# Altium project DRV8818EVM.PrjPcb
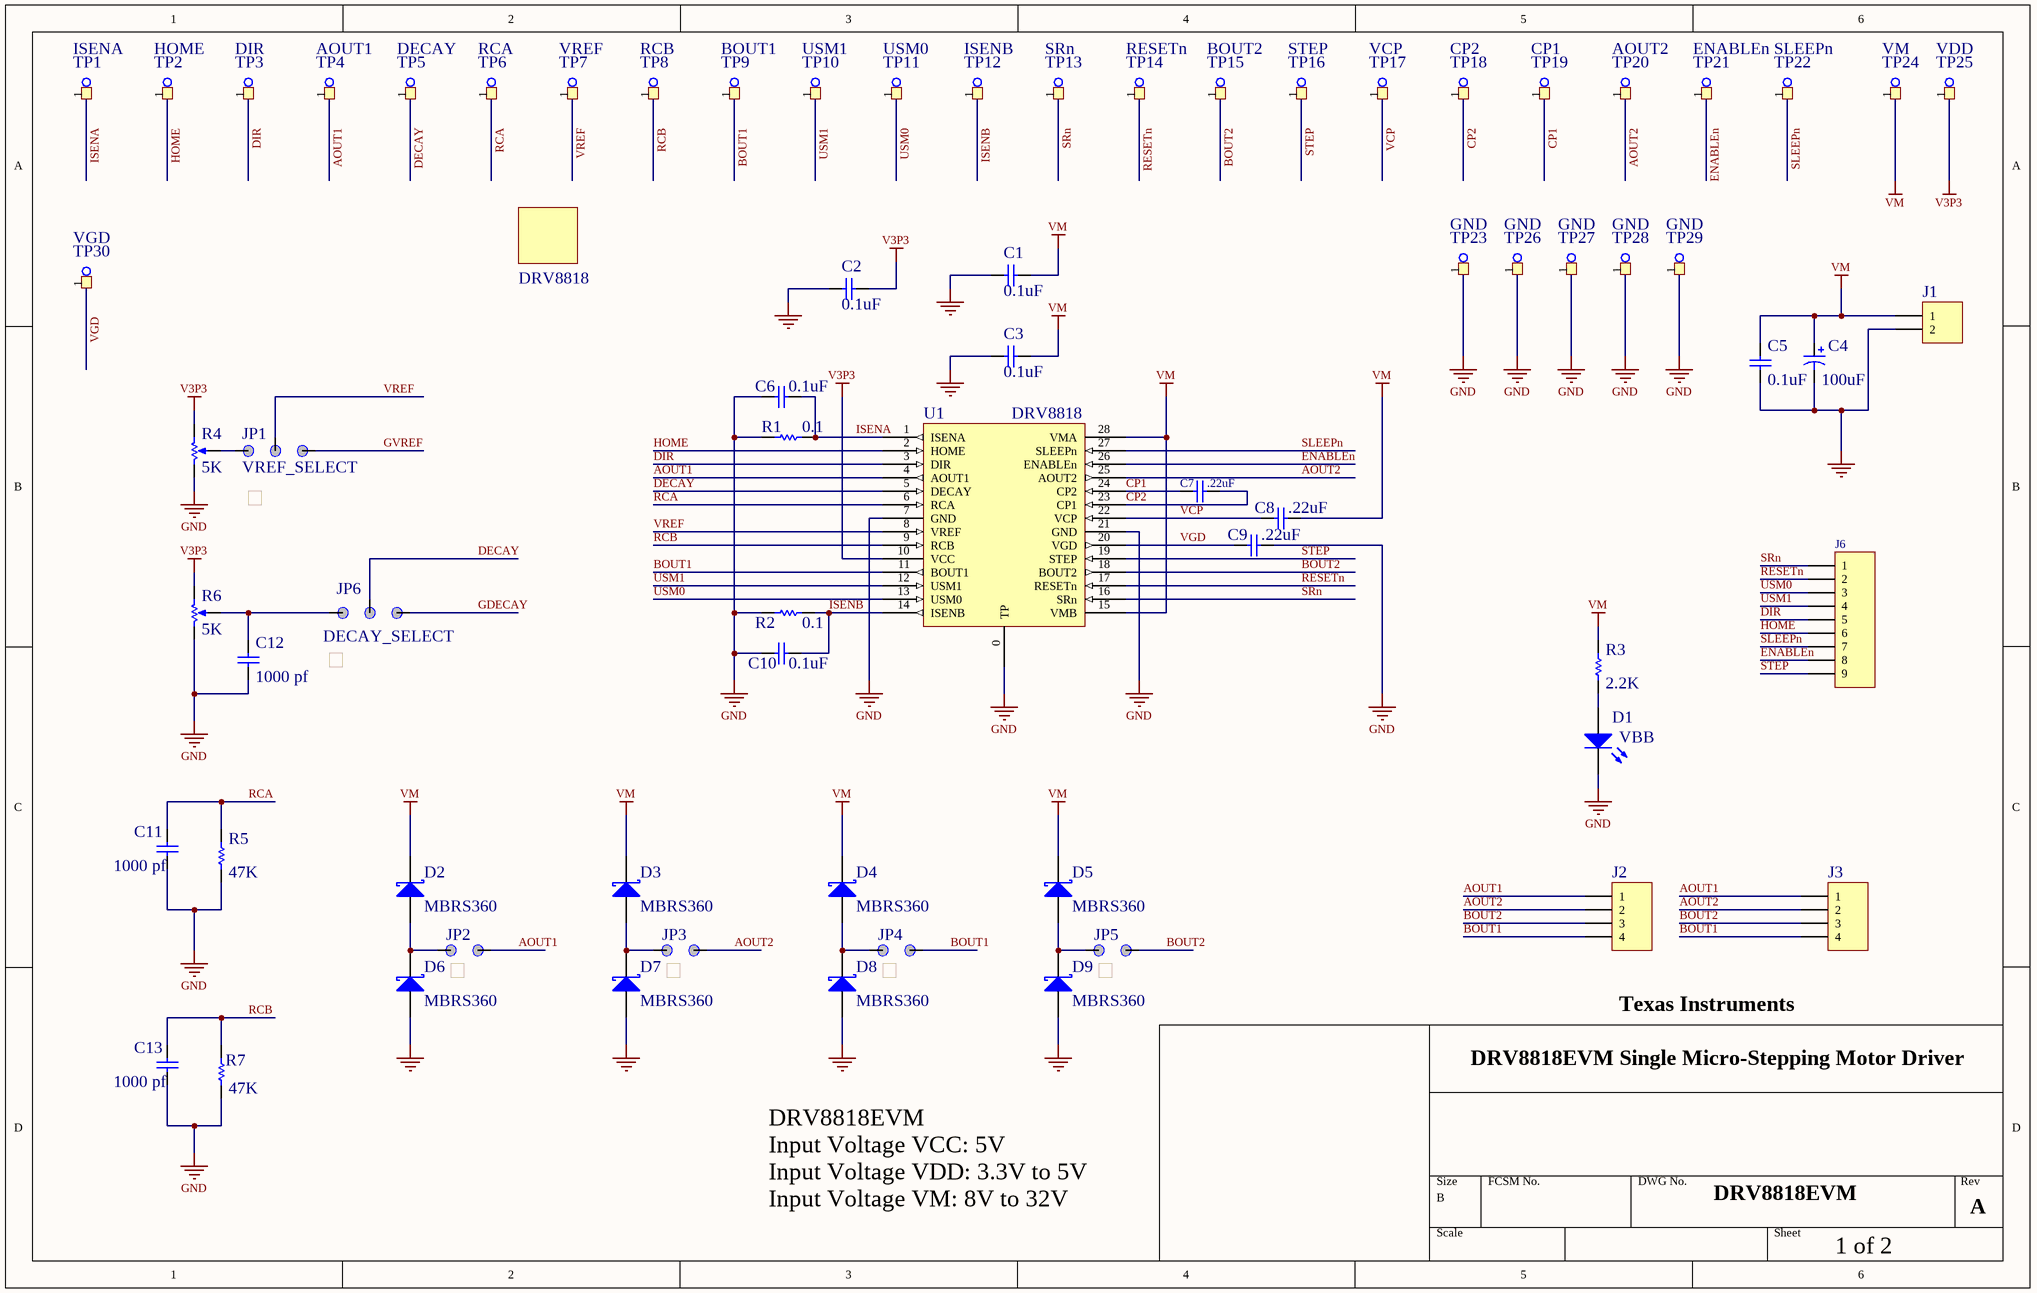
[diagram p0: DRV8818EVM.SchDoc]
2 sheets, 115 parts. Net scope: global (net labels, ports and power ports of the same name join across sheets).
Board file: DRV8818EVM.PcbDoc
Sheets:
  DRV8818EVM.SchDoc
  DRV8818EVM_MSP430.SchDoc

## Sheet DRV8818EVM.SchDoc: Texas Instruments - DRV8818 Customer EVM
size B; PageSetup: Record=PageOptions|CenterHorizontal=True|CenterVertical=True|PrintScale=1.00|XCorrection=1.00|YCorrection=1.00|PrintKind=0|BorderSize=5000000|LeftOffset=0|BottomOffset=0|Orientation=2|PaperLength=1000|PaperWidth=1000|Scale=100|PaperSource=7|PrintQuality=-4|MediaType=1|DitherType=10|PaperKind=Letter|PrintScaleMode=1

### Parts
C1  value 0.1uF  [0805]
C2  value 0.1uF  [0805]
C3  value 0.1uF  [0805]
C4  value 100uF  [RB .2/.4 SS]
C5  value 0.1uF  [0805]
C6  value 0.1uF  [0805]
C7  value .22uF  [0805]  (hidden comment: .1uF)
C8  value .22uF  [0805]  (hidden comment: .1uF)
C9  value .22uF  [0805]  (hidden comment: .1uF)
C10  value 0.1uF  [0805]
C11  value 1000 pf  [0805]
C12  value 1000 pf  [0805]
C13  value 1000 pf  [0805]
D1  VBB  [1206_LED]
D2  MBRS360  [SMC-W]
D3  MBRS360  [SMC-W]
D4  MBRS360  [SMC-W]
D5  MBRS360  [SMC-W]
D6  MBRS360  [SMC-W]
D7  MBRS360  [SMC-W]
D8  MBRS360  [SMC-W]
D9  MBRS360  [SMC-W]
J1  Header 2  [PWR_CONN2]  (value not drawn)
J2  Header 4  [HDR1X4]  (value not drawn)
J3  Header 4  [PWR_CONN4]  (value not drawn)
J6  Header 9  [HDR1X9]  (value not drawn)
JP1  VREF_SELECT  [JMP0.3]
JP2  JUMPER 2 PIN  [JMP0.2]  (value not drawn)
JP3  JUMPER 2 PIN  [JMP0.2]  (value not drawn)
JP4  JUMPER 2 PIN  [JMP0.2]  (value not drawn)
JP5  JUMPER 2 PIN  [JMP0.2]  (value not drawn)
JP6  DECAY_SELECT  [JMP0.3]
PCB1  DRV8818  [TI_LOGO]
R1  value 0.1  [2512]
R2  value 0.1  [2512]
R3  value 2.2K  [0805]  (hidden comment: Res1)
R4  value 5K  [VR5]
R5  value 47K  [0805]
R6  value 5K  [VR5]
R7  value 47K  [0805]
SHNT1  3 pin Jumper Shunt  (value not drawn)
SHNT2  3 pin Jumper Shunt  (value not drawn)
SHNT3  3 pin Jumper Shunt  (value not drawn)
SHNT4  3 pin Jumper Shunt  (value not drawn)
SHNT5  3 pin Jumper Shunt  (value not drawn)
SHNT6  3 pin Jumper Shunt  (value not drawn)
TP1  ISENA  [TEST POINT 0.052]
TP2  HOME  [TEST POINT 0.052]
TP3  DIR  [TEST POINT 0.052]
TP4  AOUT1  [TEST POINT 0.052]
TP5  DECAY  [TEST POINT 0.052]
TP6  RCA  [TEST POINT 0.052]
TP7  VREF  [TEST POINT 0.052]
TP8  RCB  [TEST POINT 0.052]
TP9  BOUT1  [TEST POINT 0.052]
TP10  USM1  [TEST POINT 0.052]
TP11  USM0  [TEST POINT 0.052]
TP12  ISENB  [TEST POINT 0.052]
TP13  SRn  [TEST POINT 0.052]
TP14  RESETn  [TEST POINT 0.052]
TP15  BOUT2  [TEST POINT 0.052]
TP16  STEP  [TEST POINT 0.052]
TP17  VCP  [TEST POINT 0.052]
TP18  CP2  [TEST POINT 0.052]
TP19  CP1  [TEST POINT 0.052]
TP20  AOUT2  [TEST POINT 0.052]
TP21  ENABLEn  [TEST POINT 0.052]
TP22  SLEEPn  [TEST POINT 0.052]
TP23  GND  [TEST POINT 0.052]
TP24  VM  [TEST POINT 0.052]
TP25  VDD  [TEST POINT 0.052]
TP26  GND  [TEST POINT 0.052]
TP27  GND  [TEST POINT 0.052]
TP28  GND  [TEST POINT 0.052]
TP29  GND  [TEST POINT 0.052]
TP30  VGD  [TEST POINT 0.052]
U1  DRV8818  [HTSSOP28 - DRV8818]

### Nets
GND: C1.1 C2.1 C3.1 C4.2 C5.1 C6.1 C9.1 C10.1 C11.2 C12.2 C13.2 D1.2(K) D6.1(A) D7.1(A) D8.1(A) D9.1(A) J1.2 R1.2 R2.2 R4.3(BOT) R5.1 R6.3(BOT) R7.1 TP23.1 TP26.1 TP27.1 TP28.1 TP29.1 U1.0(TP) U1.7(GND) U1.21(GND)
V3P3: C2.2 R4.1(TOP) R6.1(TOP) TP25.1 U1.10(VCC)
VM: C1.2 C3.2 C4.1 C5.2 C8.1 D2.2(K) D3.2(K) D4.2(K) D5.2(K) J1.1 R3.2 TP24.1 U1.15(VMB) U1.28(VMA)
AOUT1: J2.1 J3.1 JP2.2 TP4.1 U1.4(AOUT1)
AOUT2: J2.2 J3.2 JP3.2 TP20.1 U1.25(AOUT2)
BOUT1: J2.4 J3.4 JP4.2 TP9.1 U1.11(BOUT1)
BOUT2: J2.3 J3.3 JP5.2 TP15.1 U1.18(BOUT2)
CP1: C7.2 TP19.1 U1.24(CP2)
CP2: C7.1 TP18.1 U1.23(CP1)
DECAY: JP6.2 TP5.1 U1.5(DECAY)
DIR: J6.5 TP3.1 U1.3(DIR)
ENABLEn: J6.8 TP21.1 U1.26(ENABLEn)
GDECAY: JP6.1
GVREF: JP1.1
HOME: J6.6 TP2.1 U1.2(HOME)
ISENA: C6.2 R1.1 TP1.1 U1.1(ISENA)
ISENB: C10.2 R2.1 TP12.1 U1.14(ISENB)
RCA: C11.1 R5.2 TP6.1 U1.6(RCA)
RCB: C13.1 R7.2 TP8.1 U1.9(RCB)
RESETn: J6.2 TP14.1 U1.17(RESETn)
SLEEPn: J6.7 TP22.1 U1.27(SLEEPn)
SRn: J6.1 TP13.1 U1.16(SRn)
STEP: J6.9 TP16.1 U1.19(STEP)
USM0: J6.3 TP11.1 U1.13(USM0)
USM1: J6.4 TP10.1 U1.12(USM1)
VCP: C8.2 TP17.1 U1.22(VCP)
VGD: C9.2 TP30.1 U1.20(VGD)
VREF: JP1.2 TP7.1 U1.8(VREF)
NetC12_1: C12.1 JP6.3 R6.2(TAP)
NetD1_1: D1.1(A) R3.1
NetD2_1: D2.1(A) D6.2(K) JP2.1
NetD3_1: D3.1(A) D7.2(K) JP3.1
NetD4_1: D4.1(A) D8.2(K) JP4.1
NetD5_1: D5.1(A) D9.2(K) JP5.1
NetJP1_3: JP1.3 R4.2(TAP)

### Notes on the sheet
- Texas Instruments
- DRV8818EVM Single Micro-Stepping Motor Driver
- DRV8818EVM
- Input Voltage VCC: 5V
- Input Voltage VDD: 3.3V to 5V
- Input Voltage VM: 8V to 32V
- A
- 1 of 2

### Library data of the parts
C1-C3 C5 C6 C10 = Cap: Capacitor; MFG Part Number: C0805C104K5RACTU; Manufacturer: Kemet
C4 = Cap Pol1: 100uF, 50V Electrolytic Cap; MFG Part Number: ECA-1HM101; Manufacturer: Panasonic
C7-C9 = Cap: Capacitor; MFG Part Number: C0805C224K5RACTU; Manufacturer: Kemet
C11-C13 = Cap: Capacitor; MFG Part Number: C0805C102K5RACTU; Manufacturer: Kemet
D1 = LED3: LED RED Clear 1206 SMD; MFG Part Number: HBR1105W-TR; Manufacturer: Stanley Electric & Co; Value: LED RED
D2-D9 = D Schottky: 3A, 60V, Schottky Diode; MFG Part Number: MBRS360T3G; Manufacturer: On Semiconductor; Value: MBR360
J1 = Header 2: Terminal Block, 2 Pos, 200 mil pitch; MFG Part Number: OSTTA024163; Manufacturer: On Shore Technology Inc.; Value: 2 Pos
J2 = Header 4: Single Line, 4 Pos, 100 mil pitch Header Connector; MFG Part Number: PBC04SAAN; Manufacturer: Sullins; Value: 4 Pos Header
J3 = Header 4: Terminal Block, 4 Pos, 200 mil pitch; MFG Part Number: OSTTA044163; Manufacturer: On Shore Technology Inc.; Value: 4 Pos
J6 = Header 9: Control
JP1 JP6 = JUMPER 3 PIN: Single Line, 3 Pos, 100 mil pitch Header Connector; MFG Part Number: PBC03SAAN; Manufacturer: Sullins; VALUE: 3 Pos Header
JP2-JP5 = JUMPER 2 PIN: Single Line, 2 Pos, 100 mil pitch Header Connector; MFG Part Number: PBC02SAAN; Manufacturer: Sullins; VALUE: 2 Pos Header
PCB1 = TI_LOGO: CPG001 PCB Bare Board
R1 R2 = Res1: Resistor; MFG Part Number: CRA2512-FZ-R100ELF; Manufacturer: Bourns
R3 = Res1: Resistor; MFG Part Number: RC0805JR-072K2L; Manufacturer: Yageo
R4 R6 = RPot: Potentiometer; MFG Part Number: PV37Y502C01B00; Manufacturer: Murata Electronics
R5 R7 = Res1: Resistor; MFG Part Number: RC0805JR-0747KL; Manufacturer: Yageo
SHNT1-SHNT6 = ShuntJumper: Shunt Jumper
TP1-TP22 TP30 = TEST POINT: Glass Beaded Test Point; MFG Part Number: 151-101-RC; Manufacturer: Kobiconn; Value: Test Stake White
TP23 TP26-TP29 = TEST POINT: Glass Beaded Test Point; MFG Part Number: 151-103-RC; Manufacturer: Kobiconn; Value: Test Stake Black
TP24 TP25 = TEST POINT: Glass Beaded Test Point; MFG Part Number: 151-107-RC; Manufacturer: Kobiconn; Value: Test Stake Red
U1 = DRV8811: Bipolar Stepper Motor Driver With Indexer; MFG Part Number: DRV8811A2PWP; Manufacturer: Texas Instruments

## Sheet DRV8818EVM_MSP430.SchDoc
size B
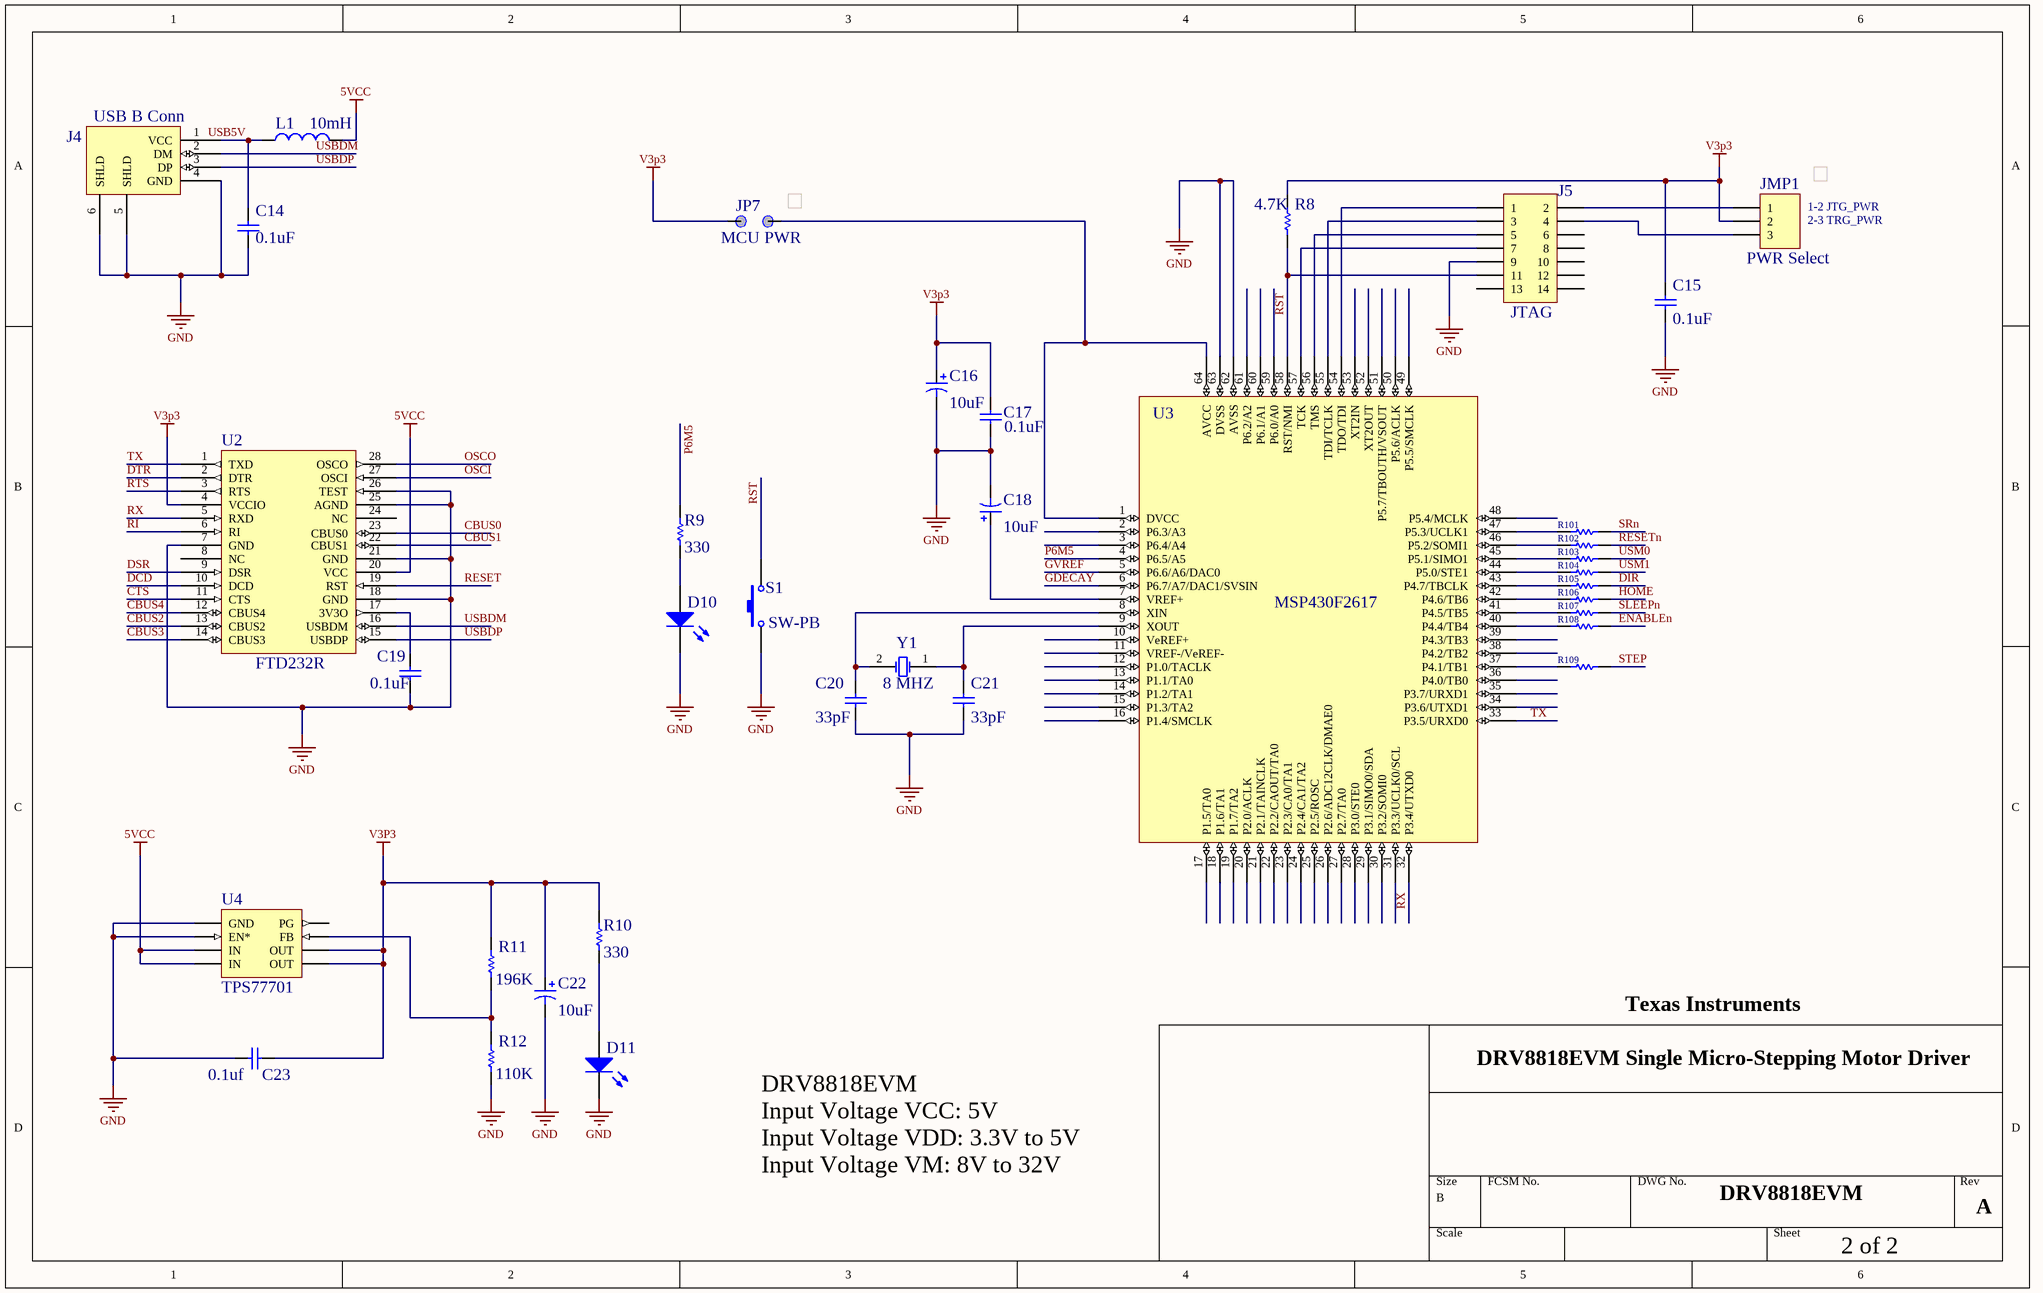
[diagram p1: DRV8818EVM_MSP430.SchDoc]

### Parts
C14  value 0.1uF  [0805]  (hidden comment: Cap)
C15  value 0.1uF  [0805]  (hidden comment: Cap)
C16  value 10uF  [RB .1/.250]  (hidden comment: Cap Pol1)
C17  value 0.1uF  [0805]  (hidden comment: Cap)
C18  value 10uF  [RB .1/.250]  (hidden comment: Cap Pol1)
C19  value 0.1uF  [0805]  (hidden comment: Cap)
C20  value 33pF  [0805]  (hidden comment: Cap)
C21  value 33pF  [0805]  (hidden comment: Cap)
C22  value 10uF  [RB .1/.250]  (hidden comment: Cap Pol1)
C23  value 0.1uf  [0805]  (hidden comment: Cap1)
D10  LED3  [1206_LED]  (value not drawn)
D11  LED3  [1206_LED]  (value not drawn)
J4  USB B Conn  [USB_CONN]
J5  JTAG  [HDR2X7]
JMP1  PWR Select  [HDR1X3]
JP7  MCU PWR  [JMP0.2]
L1  value 10mH  [0805]
R8  value 4.7K  [0805]  (hidden comment: Res1)
R9  value 330  [0805]  (hidden comment: Res2)
R10  value 330  [0805]  (hidden comment: Res2)
R11  value 196K  [0805]  (hidden comment: Res2)
R12  value 110K  [0805]  (hidden comment: Res2)
R101  Res2  [0603]  (value not drawn)
R102  Res2  [0603]  (value not drawn)
R103  Res2  [0603]  (value not drawn)
R104  Res2  [0603]  (value not drawn)
R105  Res2  [0603]  (value not drawn)
R106  Res2  [0603]  (value not drawn)
R107  Res2  [0603]  (value not drawn)
R108  Res2  [0603]  (value not drawn)
R109  Res2  [0603]  (value not drawn)
S1  SW-PB  [Pana_PB]
SHNT7  3 pin Jumper Shunt  (value not drawn)
SHNT8  3 pin Jumper Shunt  (value not drawn)
U2  FTD232R  [FT232RL]
U3  MSP430F2617  [MSP430F1612]
U4  TPS77701  [TL7726]
Y1  8 MHZ  [XTAL]

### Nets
5VCC: L1.2 U2.20(VCC) U4.3(IN) U4.4(IN)
GND: C14.1 C15.1 C16.2 C17.1 C18.2 C19.1 C20.1 C21.1 C22.2 C23.1 D10.2(K) D11.2(K) J4.4(GND) J4.5(SHLD) J4.6(SHLD) J5.9 R12.1 S1.1 U2.7(GND) U2.18(GND) U2.21(GND) U2.25(AGND) U2.26(TEST) U3.62(AVSS) U3.63(DVSS) U4.1(GND) U4.2(EN*)
V3P3: C15.2 C16.1 C17.2 C22.1 C23.2 JMP1.2 JP7.1 R8.2 R10.2 R11.2 U2.4(VCCIO) U4.5(OUT) U4.6(OUT)
CBUS0: U2.23(CBUS0)
CBUS1: U2.22(CBUS1)
CBUS2: U2.13(CBUS2)
CBUS3: U2.14(CBUS3)
CBUS4: U2.12(CBUS4)
CTS: U2.11(CTS)
DCD: U2.10(DCD)
DIR: R105.1
DSR: U2.9(DSR)
DTR: U2.2(DTR)
ENABLEn: R108.1
GDECAY: U3.6(P6.7/A7/DAC1/SVSIN)
GVREF: U3.5(P6.6/A6/DAC0)
HOME: R106.1
OSCI: U2.27(OSCI)
OSCO: U2.28(OSCO)
P6M5: R9.2 U3.4(P6.5/A5)
RESET: U2.19(RST)
RESETn: R102.1
RI: U2.6(RI)
RST: J5.11 R8.1 S1.2 U3.58(RST/NMI)
RTS: U2.3(RTS)
RX: U2.5(RXD) U3.32(P3.4/UTXD0)
SLEEPn: R107.1
SRn: R101.1
STEP: R109.1
TX: U2.1(TXD) U3.33(P3.5/URXD0)
USBDM: J4.2(DM) U2.16(USBDM)
USBDP: J4.3(DP) U2.15(USBDP)
USM0: R103.1
USM1: R104.1
NetC14_2: C14.2 J4.1(VCC) L1.1
NetC18_1: C18.1 U3.7(VREF+)
NetC19_2: C19.2 U2.17(3V3O)
NetC20_2: C20.2 U3.8(XIN) Y1.2(OSC2)
NetC21_2: C21.2 U3.9(XOUT) Y1.1(OSC1)
NetD10_1: D10.1(A) R9.1
NetD11_1: D11.1(A) R10.1
NetJ5_1: J5.1 U3.54(TDO/TDI)
NetJ5_2: J5.2 JMP1.1
NetJ5_3: J5.3 U3.55(TDI/TCLK)
NetJ5_4: J5.4 JMP1.3
NetJ5_5: J5.5 U3.56(TMS)
NetJ5_7: J5.7 U3.57(TCK)
NetJP7_2: JP7.2 U3.1(DVCC) U3.64(AVCC)
NetR11_1: R11.1 R12.2 U4.7(FB)
NetR101_2: R101.2 U3.47(P5.3/UCLK1)
NetR102_2: R102.2 U3.46(P5.2/SOMI1)
NetR103_2: R103.2 U3.45(P5.1/SIMO1)
NetR104_2: R104.2 U3.44(P5.0/STE1)
NetR105_2: R105.2 U3.43(P4.7/TBCLK)
NetR106_2: R106.2 U3.42(P4.6/TB6)
NetR107_2: R107.2 U3.41(P4.5/TB5)
NetR108_2: R108.2 U3.40(P4.4/TB4)
NetR109_2: R109.2 U3.37(P4.1/TB1)

Not connected (* = marked no-connect by the designer): J5 6 8 10 12 13 14; U2 8(NC) 24(NC); U3 2(P6.3/A3) 3(P6.4/A4) 10(VeREF+) 11(VREF-/VeREF-) 12(P1.0/TACLK) 13(P1.1/TA0) 14(P1.2/TA1) 15(P1.3/TA2) 16(P1.4/SMCLK) 17(P1.5/TA0) 18(P1.6/TA1) 19(P1.7/TA2) 20(P2.0/ACLK) 21(P2.1/TAINCLK) 22(P2.2/CAOUT/TA0) 23(P2.3/CA0/TA1) 24(P2.4/CA1/TA2) 25(P2.5/ROSC) 26(P2.6/ADC12CLK/DMAE0) 27(P2.7/TA0) 28(P3.0/STE0) 29(P3.1/SIMO0/SDA) 30(P3.2/SOMI0) 31(P3.3/UCLK0/SCL) 34(P3.6/UTXD1) 35(P3.7/URXD1) 36(P4.0/TB0) 38(P4.2/TB2) 39(P4.3/TB3) 48(P5.4/MCLK) 49(P5.5/SMCLK) 50(P5.6/ACLK) 51(P5.7/TBOUTH/VSOUT) 52(XT2OUT) 53(XT2IN) 59(P6.0/A0) 60(P6.1/A1) 61(P6.2/A2); U4 8(PG)

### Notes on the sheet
- 1-2 JTG_PWR
- 2-3 TRG_PWR
- Texas Instruments
- DRV8818EVM
- DRV8818EVM Single Micro-Stepping Motor Driver
- Input Voltage VCC: 5V
- Input Voltage VDD: 3.3V to 5V
- Input Voltage VM: 8V to 32V
- A
- 2 of 2
- Labels drawn without touching a wire or pin: USB5V

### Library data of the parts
C14 C15 C17 C19 = Cap: as C1 on sheet DRV8818EVM
C16 C18 C22 = Cap Pol1: 10uF, 25V Electrolytic Cap (Radial); MFG Part Number: UVR1E100MDD; Manufacturer: Nichicon
C20 C21 = Cap: Capacitor; MFG Part Number: CC0805JRNP09BN330; Manufacturer: Yageo
C23 = Cap1: Capacitor; MFG Part Number: C0805C104K5RACTU; Manufacturer: Kemet
D10 D11 = LED3: as D1 on sheet DRV8818EVM
J4 = USB_B_CONN: USB B Style Connector; MFG Part Number: 67068-8000; Manufacturer: Molex; Value: USB B
J5 = Header 7X2H: Header, 7-Pin, Dual row, Right Angle; MFG Part Number: PBC07DAAN; Manufacturer: Sullins; Value: 14 Pos Header
JMP1 = Header 3: Single Line, 3 Pos, 100 mil pitch Header Connector; MFG Part Number: PBC03SAAN; Manufacturer: Sullins; Value: 3 Pos Header
JP7 = JUMPER 2 PIN: as JP2 on sheet DRV8818EVM
L1 = Inductor: Ferrite Bead 1.5A 40 ohm 0805 SMD; MFG Part Number: MI0805K400R-10; Manufacturer: Steward
R8 = Res1: Resistor; MFG Part Number: RC0805JR-074K7L; Manufacturer: Yageo
R9 R10 = Res2: Resistor; MFG Part Number: RC0805JR-07330RL; Manufacturer: Yageo
R11 = Res2: Resistor; MFG Part Number: 9C08052A1963FKHFT; Manufacturer: Yageo
R12 = Res2: Resistor; MFG Part Number: RC0805JR-07110KL; Manufacturer: Yageo
R101-R109 = Res2: Resistor; MFG Part Number: RC0603FR-073K3L; Manufacturer: Yageo; Value: 3300
S1 = SW-PB: Switch; MFG Part Number: EVQ-11A04M; Manufacturer: Panasonic; Value: Push Button
SHNT7 SHNT8 = ShuntJumper: Shunt Jumper
U2 = FT232R: USB Chip; MFG Part Number: 604-00043; Manufacturer: FTDI; Value: USB Driver
U3 = MSP430F1612: MSp430 Microcontroller; Manufacturer: Texas Instruments; Value: MSP430 MCU
U4 = TPS77701: 750 mA LDO 8-SOIC; MFG Part Number: TPS77701D; Manufacturer: Texas Instruments
Y1 = XTAL: Crystal Oscillator; MFG Part Number: ECS-80-20-4; Manufacturer: ECS Inc.

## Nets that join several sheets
GND: DRV8818EVM (31 pins), DRV8818EVM_MSP430 (27 pins)
V3P3: DRV8818EVM (5 pins), DRV8818EVM_MSP430 (13 pins)
DIR: DRV8818EVM (J6.5 TP3.1 U1.3), DRV8818EVM_MSP430 (R105.1)
ENABLEn: DRV8818EVM (J6.8 TP21.1 U1.26), DRV8818EVM_MSP430 (R108.1)
GDECAY: DRV8818EVM (JP6.1), DRV8818EVM_MSP430 (U3.6)
GVREF: DRV8818EVM (JP1.1), DRV8818EVM_MSP430 (U3.5)
HOME: DRV8818EVM (J6.6 TP2.1 U1.2), DRV8818EVM_MSP430 (R106.1)
RESETn: DRV8818EVM (J6.2 TP14.1 U1.17), DRV8818EVM_MSP430 (R102.1)
SLEEPn: DRV8818EVM (J6.7 TP22.1 U1.27), DRV8818EVM_MSP430 (R107.1)
SRn: DRV8818EVM (J6.1 TP13.1 U1.16), DRV8818EVM_MSP430 (R101.1)
STEP: DRV8818EVM (J6.9 TP16.1 U1.19), DRV8818EVM_MSP430 (R109.1)
USM0: DRV8818EVM (J6.3 TP11.1 U1.13), DRV8818EVM_MSP430 (R103.1)
USM1: DRV8818EVM (J6.4 TP10.1 U1.12), DRV8818EVM_MSP430 (R104.1)

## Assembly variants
DRV8818EVM: not fitted D2 D3 D4 D5 D6 D7 D8 D9 JP2 JP3 JP4 JP5 SHNT3 SHNT4 SHNT5 SHNT6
